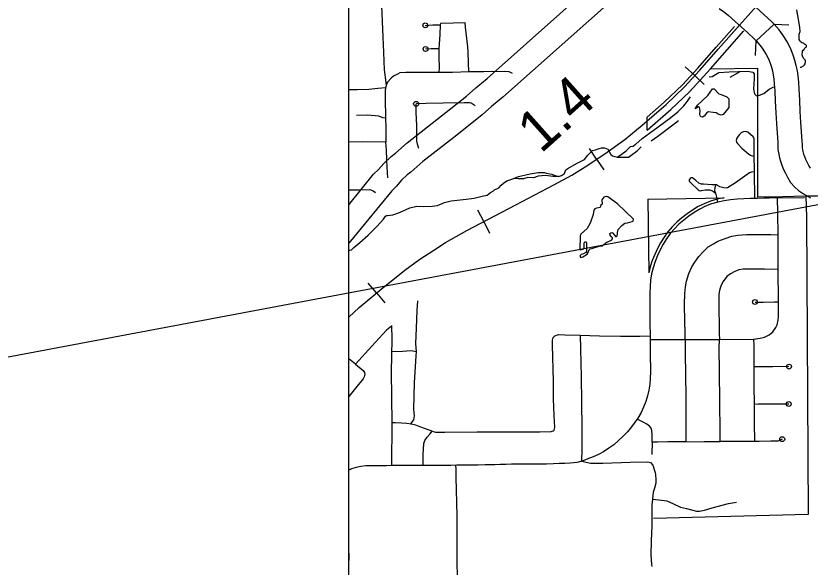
# Model space of a CAD drawing. Extents: x 1367863 to 1368197, y 380048 to 380261.
# Drawn here: x 1367946.24 to 1367977.76, y 380109.6 to 380131.45 of the extents above; entities that cross this region are included whole.
import ezdxf

# ---------------------------------------------------------------- set-up
doc = ezdxf.new("R2010")
doc.units = 0
for name, color, linetype in [('Level 10', 7, 'Continuous'), ('Level 33', 7, 'Continuous'), ('Level 34', 7, 'Continuous'), ('Level 35', 7, 'Continuous'), ('Level 37', 7, 'Continuous'), ('Level 40', 7, 'Continuous'), ('Level 43', 7, 'Continuous'), ('Level 48', 7, 'Continuous'), ('Level 6', 7, 'Continuous'), ('R_Draft', 7, 'Continuous'), ('R_No Plot', 7, 'Continuous')]:
    doc.layers.add(name, color=color, linetype=linetype)

msp = doc.modelspace()

# ---------------------------------------------------------------- linework, layer by layer
at = {"layer": 'Level 10'}
for points in [[(1367959.444, 380123.965), (1367960.435, 380125.172), (1367960.622, 380125.358), (1367960.839, 380125.604), (1367961.127, 380125.881), (1367961.296, 380126.009), (1367961.763, 380126.42), (1367963.132, 380127.482), (1367964.116, 380128.267), (1367964.487, 380128.603), (1367964.936, 380128.963), (1367969.509, 380133.035)], [(1367970.154, 380132.31), (1367965.562, 380128.221), (1367965.116, 380127.864), (1367964.745, 380127.528), (1367963.732, 380126.72), (1367962.381, 380125.672), (1367961.91, 380125.257), (1367961.759, 380125.142), (1367961.54, 380124.932), (1367961.328, 380124.692), (1367961.153, 380124.518), (1367959.444, 380122.436)], [(1367976.324, 380131.118), (1367976.233, 380131.216), (1367975.922, 380131.507), (1367975.438, 380131.938), (1367975.133, 380132.224), (1367974.894, 380132.402), (1367974.719, 380132.53)], [(1367974.147, 380131.746), (1367974.318, 380131.621), (1367974.51, 380131.478), (1367974.783, 380131.222), (1367975.267, 380130.791), (1367975.546, 380130.53), (1367975.614, 380130.457)], [(1367977.772, 380125.411), (1367977.71, 380125.521), (1367977.641, 380125.654), (1367977.588, 380125.761), (1367977.545, 380125.862), (1367977.51, 380125.972), (1367977.48, 380126.075), (1367977.461, 380126.154), (1367977.454, 380126.204), (1367977.45, 380126.238), (1367977.449, 380126.354), (1367977.441, 380126.488), (1367977.386, 380127.24), (1367977.365, 380127.653), (1367977.342, 380128.124), (1367977.32, 380128.534), (1367977.302, 380128.824), (1367977.278, 380129.075), (1367977.249, 380129.27), (1367977.207, 380129.484), (1367977.154, 380129.686), (1367977.098, 380129.858), (1367977.004, 380130.104), (1367976.857, 380130.404), (1367976.654, 380130.714), (1367976.528, 380130.899), (1367976.324, 380131.118), (1367975.614, 380130.457)], [(1367975.614, 380130.457), (1367975.767, 380130.292), (1367975.847, 380130.175), (1367976.013, 380129.922), (1367976.114, 380129.717), (1367976.183, 380129.536), (1367976.222, 380129.414), (1367976.261, 380129.266), (1367976.293, 380129.104), (1367976.315, 380128.958), (1367976.335, 380128.749), (1367976.351, 380128.479), (1367976.373, 380128.074), (1367976.396, 380127.604), (1367976.418, 380127.18), (1367976.473, 380126.424), (1367976.479, 380126.321), (1367976.481, 380126.184), (1367976.491, 380126.082), (1367976.508, 380125.967), (1367976.542, 380125.827), (1367976.582, 380125.691), (1367976.633, 380125.528), (1367976.705, 380125.357), (1367976.777, 380125.212), (1367976.857, 380125.059), (1367976.976, 380124.846), (1367977.144, 380124.657), (1367977.296, 380124.529), (1367977.49, 380124.399), (1367977.773, 380124.236)]]:
    msp.add_lwpolyline(points, dxfattribs=at)
at = {"layer": 'Level 33'}
for points in [[(1367960.702, 380134.32), (1367960.703, 380133.913), (1367960.732, 380132.946), (1367960.749, 380131.842), (1367960.82, 380129.997), (1367960.855, 380129.315), (1367960.912, 380128.815), (1367960.929, 380128.674)], [(1367962.485, 380131.074), (1367962.786, 380131.093), (1367963.081, 380131.098)], [(1367963.081, 380131.098), (1367963.062, 380130.699), (1367963.026, 380130.151), (1367963.022, 380129.798), (1367963.031, 380129.418), (1367963.026, 380129.201)], [(1367963.085, 380131.152), (1367963.081, 380131.098)], [(1367964.072, 380131.175), (1367963.596, 380131.166), (1367963.085, 380131.152)], [(1367964.207, 380129.228), (1367964.198, 380129.585), (1367964.185, 380130.025), (1367964.167, 380130.228), (1367964.108, 380130.772), (1367964.076, 380131.003), (1367964.072, 380131.175)], [(1367962.497, 380130.139), (1367962.723, 380130.16), (1367963.026, 380130.151)], [(1367965.947, 380129.172), (1367965.819, 380129.237), (1367965.629, 380129.246), (1367964.814, 380129.237), (1367964.207, 380129.228), (1367963.56, 380129.205), (1367963.026, 380129.201), (1367962.374, 380129.201), (1367961.709, 380129.201), (1367961.474, 380129.187), (1367961.379, 380129.142), (1367961.225, 380129.056), (1367961.125, 380128.974), (1367960.999, 380128.838), (1367960.949, 380128.748), (1367960.929, 380128.674)], [(1367960.905, 380128.593), (1367960.607, 380128.57), (1367960.246, 380128.534), (1367959.776, 380128.52), (1367959.444, 380128.514)], [(1367960.929, 380128.674), (1367960.905, 380128.593), (1367960.894, 380128.476), (1367960.891, 380128.175), (1367960.908, 380127.394)], [(1367964.461, 380127.879), (1367964.302, 380127.984), (1367964.24, 380128.007), (1367964.023, 380128.007), (1367963.194, 380127.987), (1367962.524, 380127.982), (1367962.119, 380127.964)], [(1367962.232, 380126.193), (1367962.169, 380126.36), (1367962.152, 380126.483), (1367962.144, 380127.11), (1367962.127, 380127.619), (1367962.119, 380127.964)], [(1367960.908, 380127.394), (1367960.796, 380127.412), (1367960.641, 380127.476), (1367960.499, 380127.49), (1367960.177, 380127.508), (1367959.752, 380127.501)], [(1367960.908, 380127.394), (1367960.917, 380127.048), (1367960.924, 380126.439)], [(1367975.563, 380124.212), (1367975.553, 380125.264), (1367975.538, 380125.974), (1367975.538, 380126.599), (1367975.494, 380126.653), (1367975.285, 380126.837), (1367975.241, 380126.857), (1367975.186, 380126.867), (1367975.102, 380126.852), (1367975.023, 380126.817), (1367974.938, 380126.733), (1367974.874, 380126.638), (1367974.834, 380126.574), (1367974.824, 380126.51), (1367974.839, 380126.44), (1367974.869, 380126.385), (1367975.042, 380126.212), (1367975.32, 380125.969), (1367975.385, 380125.924), (1367975.414, 380125.909), (1367975.474, 380125.899), (1367975.533, 380125.894)], [(1367960.924, 380126.439), (1367959.979, 380126.453), (1367959.444, 380126.447)], [(1367961.002, 380125.033), (1367960.972, 380125.452), (1367960.961, 380125.741), (1367960.941, 380126.126), (1367960.924, 380126.439)], [(1367975.553, 380125.264), (1367975.429, 380125.259), (1367975.345, 380125.225), (1367974.79, 380124.828), (1367974.477, 380124.634), (1367974.428, 380124.624), (1367974.338, 380124.629), (1367974.17, 380124.679), (1367974.085, 380124.729), (1367974.041, 380124.748), (1367973.996, 380124.753), (1367973.862, 380124.758), (1367973.525, 380124.773), (1367973.451, 380124.773), (1367973.401, 380124.793), (1367973.337, 380124.818), (1367973.218, 380124.922), (1367973.084, 380125.031), (1367973.039, 380125.036), (1367972.995, 380125.001), (1367972.955, 380124.947), (1367972.955, 380124.927), (1367972.96, 380124.897), (1367973.029, 380124.823), (1367973.317, 380124.555), (1367973.352, 380124.53), (1367973.406, 380124.52), (1367973.451, 380124.525), (1367973.595, 380124.56), (1367973.654, 380124.56), (1367973.758, 380124.55), (1367973.882, 380124.52), (1367973.922, 380124.486), (1367973.996, 380124.416), (1367974.011, 380124.367), (1367974.036, 380124.262), (1367974.084, 380124.067)], [(1367973.996, 380124.753), (1367973.976, 380124.634), (1367973.961, 380124.53), (1367973.996, 380124.416)], [(1367959.444, 380124.557), (1367959.832, 380124.557), (1367960.285, 380124.563), (1367960.356, 380124.546), (1367960.414, 380124.514), (1367960.508, 380124.449)], [(1367977.535, 380124.24), (1367976.137, 380124.228), (1367975.93, 380124.222), (1367975.661, 380124.215), (1367975.393, 380124.206), (1367975.128, 380124.195), (1367974.864, 380124.179), (1367974.603, 380124.156), (1367974.344, 380124.12), (1367974.09, 380124.068), (1367973.842, 380123.995), (1367973.603, 380123.9), (1367973.373, 380123.786), (1367973.153, 380123.656), (1367972.941, 380123.513), (1367972.738, 380123.358), (1367972.547, 380123.191), (1367972.369, 380123.011), (1367972.204, 380122.819), (1367972.053, 380122.616), (1367971.919, 380122.401), (1367971.801, 380122.177), (1367971.696, 380121.945), (1367971.603, 380121.708), (1367971.526, 380121.466), (1367971.467, 380121.22), (1367971.428, 380120.969), (1367971.406, 380120.716), (1367971.395, 380120.461), (1367971.394, 380120.203), (1367971.396, 380119.944), (1367971.397, 380119.682), (1367971.398, 380119.419), (1367971.401, 380119.154), (1367971.404, 380118.888), (1367971.408, 380118.622), (1367971.411, 380118.359), (1367971.413, 380118.099), (1367971.415, 380117.842), (1367971.419, 380117.588), (1367971.422, 380117.339), (1367971.414, 380117.094), (1367971.392, 380116.853), (1367971.353, 380116.617), (1367971.299, 380116.387), (1367971.23, 380116.164), (1367971.145, 380115.943), (1367971.046, 380115.725), (1367970.918, 380115.501), (1367970.777, 380115.302), (1367970.663, 380115.153), (1367970.503, 380114.964), (1367970.332, 380114.785), (1367970.153, 380114.618), (1367969.971, 380114.449), (1367969.771, 380114.313), (1367969.557, 380114.172), (1367969.362, 380114.063), (1367969.146, 380113.974), (1367968.934, 380113.891), (1367968.749, 380113.815), (1367968.494, 380113.751), (1367968.234, 380113.722), (1367968.027, 380113.709), (1367967.793, 380113.699), (1367967.566, 380113.69), (1367967.3, 380113.68)], [(1367976.502, 380120.12), (1367976.49, 380121.4), (1367976.483, 380122.769), (1367976.477, 380123.621), (1367976.463, 380124.263)], [(1367972.802, 380118.622), (1367972.792, 380118.879), (1367972.786, 380119.353), (1367972.773, 380120.006), (1367972.779, 380120.441), (1367972.805, 380120.71), (1367972.85, 380120.934), (1367972.939, 380121.234), (1367973.067, 380121.497), (1367973.176, 380121.689), (1367973.336, 380121.906), (1367973.509, 380122.098), (1367973.713, 380122.29), (1367973.925, 380122.418), (1367974.091, 380122.521), (1367974.385, 380122.629), (1367974.654, 380122.713), (1367974.89, 380122.757), (1367975.236, 380122.777), (1367975.824, 380122.777), (1367976.195, 380122.783), (1367976.483, 380122.769)], [(1367976.49, 380121.4), (1367975.946, 380121.414), (1367975.102, 380121.407), (1367974.922, 380121.382), (1367974.762, 380121.318), (1367974.59, 380121.222), (1367974.449, 380121.113), (1367974.302, 380120.914), (1367974.232, 380120.78), (1367974.18, 380120.652), (1367974.155, 380120.562), (1367974.136, 380120.422), (1367974.136, 380120.178), (1367974.136, 380119.705), (1367974.142, 380119.302), (1367974.148, 380118.854), (1367974.157, 380118.622)], [(1367961.891, 380115.265), (1367962.029, 380115.442), (1367962.051, 380115.593), (1367962.036, 380115.864), (1367962.059, 380116.898), (1367962.127, 380117.978), (1367962.142, 380118.136), (1367962.104, 380118.461), (1367962.134, 380119.065), (1367962.165, 380119.767), (1367962.187, 380120.159)], [(1367975.506, 380118.635), (1367975.773, 380118.668), (1367975.94, 380118.719), (1367976.125, 380118.809), (1367976.272, 380118.931), (1367976.4, 380119.091), (1367976.451, 380119.206), (1367976.49, 380119.385), (1367976.502, 380119.545), (1367976.496, 380119.788), (1367976.502, 380120.12)], [(1367975.569, 380120.107), (1367975.895, 380120.107), (1367976.343, 380120.114), (1367976.502, 380120.12)], [(1367961.14, 380119.148), (1367960.942, 380118.989), (1367960.369, 380118.363), (1367959.72, 380117.646)], [(1367961.14, 380119.173), (1367961.153, 380118.638), (1367961.135, 380117.34), (1367961.154, 380115.317)], [(1367962.759, 380114.984), (1367962.887, 380114.95), (1367963.258, 380114.95), (1367964.543, 380114.963), (1367965.612, 380114.957), (1367967.032, 380114.957), (1367967.486, 380114.97), (1367967.556, 380114.995), (1367967.601, 380115.021), (1367967.627, 380115.13), (1367967.601, 380115.61), (1367967.569, 380116.275), (1367967.569, 380116.953), (1367967.531, 380118.409), (1367967.537, 380118.601), (1367967.556, 380118.697), (1367967.627, 380118.768), (1367967.767, 380118.819), (1367968.023, 380118.812), (1367968.637, 380118.787)], [(1367968.637, 380118.787), (1367969.392, 380118.768), (1367970.23, 380118.755), (1367970.998, 380118.755), (1367971.406, 380118.762)], [(1367968.637, 380118.787), (1367968.65, 380118.249), (1367968.669, 380117.136), (1367968.682, 380116.141), (1367968.695, 380115.117), (1367968.701, 380114.464), (1367968.695, 380114.099), (1367968.689, 380113.959), (1367968.682, 380113.798)], [(1367971.408, 380118.616), (1367972.802, 380118.622)], [(1367972.802, 380118.622), (1367972.802, 380118.078), (1367972.821, 380116.344), (1367972.827, 380115.064), (1367972.827, 380114.565)], [(1367972.802, 380118.622), (1367974.157, 380118.622)], [(1367974.189, 380114.578), (1367974.182, 380114.956), (1367974.176, 380116.152), (1367974.157, 380117.349), (1367974.15, 380118.296), (1367974.157, 380118.622)], [(1367974.157, 380118.622), (1367975.506, 380118.635)], [(1367975.506, 380118.635), (1367975.526, 380118.398), (1367975.526, 380117.534), (1367975.526, 380116.799), (1367975.532, 380116.05), (1367975.538, 380115.301), (1367975.551, 380114.584)], [(1367962.142, 380118.136), (1367961.923, 380118.167), (1367961.584, 380118.151), (1367961.146, 380118.137)], [(1367959.72, 380117.646), (1367959.444, 380117.851)], [(1367959.72, 380117.646), (1367960.022, 380117.397), (1367960.067, 380117.314), (1367960.082, 380117.246), (1367960.052, 380117.14), (1367960.014, 380117.065), (1367959.773, 380116.763), (1367959.444, 380116.361)], [(1367976.918, 380117.547), (1367976.272, 380117.541), (1367975.78, 380117.541), (1367975.526, 380117.534)], [(1367976.905, 380116.063), (1367976.579, 380116.063), (1367975.978, 380116.063), (1367975.69, 380116.056), (1367975.532, 380116.05)], [(1367961.154, 380115.317), (1367961.142, 380113.625)], [(1367962.759, 380114.984), (1367962.592, 380115.042), (1367962.311, 380115.15), (1367962.106, 380115.227), (1367961.921, 380115.259), (1367961.754, 380115.291), (1367961.537, 380115.304), (1367961.3, 380115.317), (1367961.154, 380115.317)], [(1367971.484, 380114.552), (1367971.484, 380114.84), (1367971.478, 380115.02), (1367971.452, 380115.103), (1367971.388, 380115.18), (1367971.279, 380115.263), (1367971.132, 380115.34), (1367970.895, 380115.468)], [(1367962.394, 380113.627), (1367962.4, 380114.062), (1367962.432, 380114.504), (1367962.471, 380114.613), (1367962.56, 380114.747), (1367962.669, 380114.862), (1367962.759, 380114.984)], [(1367976.65, 380114.668), (1367976.49, 380114.591), (1367976.202, 380114.591), (1367975.728, 380114.584), (1367975.551, 380114.584)], [(1367971.484, 380114.552), (1367971.479, 380114.061)], [(1367972.827, 380114.565), (1367972.105, 380114.559), (1367971.695, 380114.552), (1367971.484, 380114.552)], [(1367972.827, 380114.565), (1367973.549, 380114.572), (1367974.189, 380114.578)], [(1367975.551, 380114.584), (1367974.189, 380114.578)], [(1367967.3, 380113.68), (1367967.061, 380113.677), (1367966.811, 380113.68), (1367966.626, 380113.677), (1367966.376, 380113.674), (1367966.143, 380113.674), (1367965.899, 380113.676), (1367965.695, 380113.663), (1367965.461, 380113.661), (1367965.244, 380113.658), (1367965.049, 380113.655), (1367964.857, 380113.648), (1367964.569, 380113.642), (1367964.396, 380113.645), (1367964.169, 380113.642), (1367963.952, 380113.639), (1367963.731, 380113.635), (1367963.504, 380113.632), (1367963.296, 380113.632)], [(1367963.296, 380113.632), (1367961.262, 380113.62), (1367961.163, 380113.62), (1367960.945, 380113.618), (1367960.732, 380113.616), (1367960.522, 380113.616), (1367960.318, 380113.614), (1367960.12, 380113.607), (1367959.926, 380113.587), (1367959.737, 380113.55), (1367959.554, 380113.491), (1367959.444, 380113.437)], [(1367963.826, 380107.793), (1367963.796, 380108.304), (1367963.762, 380108.973), (1367963.748, 380110.034), (1367963.743, 380111.627), (1367963.714, 380113.161), (1367963.705, 380113.479), (1367963.695, 380113.635)], [(1367959.444, 380110.156), (1367959.448, 380110.111), (1367959.444, 380109.864)]]:
    msp.add_lwpolyline(points, dxfattribs=at)
for centre in [(1367962.485, 380131.074), (1367962.497, 380130.139), (1367962.119, 380127.964), (1367975.569, 380120.107), (1367976.918, 380117.547), (1367976.905, 380116.063), (1367976.65, 380114.668)]:
    msp.add_circle(centre, 0.097, dxfattribs=at)
at = {"layer": 'Level 34'}
for points in [[(1367968.682, 380113.798), (1367969.043, 380113.722), (1367969.525, 380113.722), (1367970.611, 380113.752), (1367971.316, 380113.77), (1367971.425, 380113.746), (1367971.509, 380113.638), (1367971.6, 380113.39), (1367971.618, 380113.27), (1367971.636, 380113.058), (1367971.63, 380112.92), (1367971.582, 380112.733), (1367971.534, 380112.57), (1367971.509, 380112.431), (1367971.503, 380112.298)], [(1367971.503, 380112.298), (1367971.481, 380112.063), (1367971.481, 380111.63), (1367971.468, 380111.222), (1367971.451, 380110.654), (1367971.439, 380110.091), (1367971.46, 380109.7), (1367971.477, 380109.616)], [(1367971.503, 380112.298), (1367971.757, 380112.268), (1367972.064, 380112.22), (1367972.33, 380112.111), (1367972.613, 380111.979), (1367972.854, 380111.924), (1367973.047, 380111.864), (1367973.252, 380111.822), (1367973.367, 380111.822), (1367973.566, 380111.858), (1367973.873, 380111.954), (1367974.516, 380112.117), (1367974.83, 380112.178)]]:
    msp.add_lwpolyline(points, dxfattribs=at)
at = {"layer": 'Level 35'}
for points in [[(1367977.363, 380129.414), (1367977.396, 380129.42), (1367977.497, 380129.467), (1367977.53, 380129.504), (1367977.556, 380129.546), (1367977.56, 380129.584), (1367977.568, 380129.613), (1367977.577, 380129.63), (1367977.577, 380129.663), (1367977.572, 380129.693), (1367977.547, 380129.71), (1367977.53, 380129.726), (1367977.514, 380129.739), (1367977.505, 380129.764), (1367977.48, 380129.789), (1367977.468, 380129.831), (1367977.442, 380129.902), (1367977.442, 380129.944), (1367977.451, 380129.994), (1367977.451, 380130.045), (1367977.484, 380130.087), (1367977.518, 380130.116), (1367977.539, 380130.154), (1367977.572, 380130.191), (1367977.602, 380130.216), (1367977.606, 380130.246), (1367977.606, 380130.279), (1367977.585, 380130.304), (1367977.535, 380130.33), (1367977.518, 380130.342), (1367977.48, 380130.363), (1367977.447, 380130.376), (1367977.409, 380130.392), (1367977.371, 380130.422), (1367977.35, 380130.476), (1367977.325, 380130.518), (1367977.325, 380130.577), (1367977.325, 380130.627), (1367977.321, 380130.665), (1367977.321, 380130.702), (1367977.321, 380130.723), (1367977.359, 380130.828), (1367977.346, 380130.991), (1367977.308, 380131.239), (1367977.225, 380131.683)], [(1367973.2, 380127.771), (1367973.284, 380127.909), (1367973.703, 380128.295), (1367973.883, 380128.555), (1367973.942, 380128.555), (1367974.13, 380128.354), (1367974.227, 380128.333), (1367974.448, 380128.236), (1367974.528, 380128.157), (1367974.536, 380128.052), (1367974.532, 380127.926), (1367974.524, 380127.817), (1367974.428, 380127.683), (1367974.302, 380127.541), (1367974.231, 380127.52), (1367974.105, 380127.558), (1367974.03, 380127.608), (1367973.904, 380127.625), (1367973.716, 380127.641), (1367973.644, 380127.599), (1367973.548, 380127.47), (1367973.485, 380127.44), (1367973.435, 380127.449), (1367973.389, 380127.482), (1367973.385, 380127.541), (1367973.385, 380127.57), (1367973.393, 380127.687), (1367973.381, 380127.767), (1367973.36, 380127.813), (1367973.322, 380127.838), (1367973.2, 380127.771)], [(1367975.554, 380128.356), (1367975.625, 380128.281), (1367975.742, 380128.302), (1367975.918, 380128.377), (1367976.128, 380128.541), (1367976.32, 380128.633)], [(1367967.769, 380125.08), (1367967.886, 380125.118), (1367968.011, 380125.206), (1367968.058, 380125.344), (1367968.145, 380125.399), (1367968.485, 380125.595), (1367968.807, 380125.763), (1367968.929, 380125.926), (1367969.117, 380126.111), (1367969.243, 380126.136), (1367969.381, 380126.19), (1367969.481, 380126.224), (1367969.594, 380126.224), (1367969.728, 380126.169), (1367969.846, 380125.96), (1367969.909, 380125.901), (1367970.101, 380125.843)], [(1367959.444, 380122.153), (1367959.489, 380122.156), (1367959.556, 380122.181), (1367959.644, 380122.265), (1367959.891, 380122.47), (1367960.218, 380122.759), (1367960.565, 380123.103), (1367960.825, 380123.392), (1367960.9, 380123.505), (1367960.951, 380123.53), (1367960.98, 380123.538), (1367961.194, 380123.568), (1367961.462, 380123.656), (1367961.872, 380123.836), (1367962.148, 380123.903), (1367962.404, 380123.895), (1367962.76, 380123.907), (1367962.973, 380123.936), (1367963.25, 380124.05), (1367963.505, 380124.121), (1367964.113, 380124.184), (1367964.418, 380124.221), (1367964.737, 380124.301), (1367964.942, 380124.343), (1367965.076, 380124.443), (1367965.197, 380124.515), (1367965.239, 380124.561), (1367965.323, 380124.594), (1367965.398, 380124.636), (1367965.49, 380124.741), (1367965.591, 380124.816), (1367965.721, 380124.908), (1367965.993, 380125.001), (1367966.177, 380125.089), (1367966.642, 380125.189), (1367966.96, 380125.239), (1367967.216, 380125.239), (1367967.287, 380125.218), (1367967.425, 380125.189), (1367967.501, 380125.176), (1367967.597, 380125.135), (1367967.769, 380125.08)], [(1367967.769, 380125.08), (1367967.551, 380125.08), (1367967.258, 380125.118), (1367966.964, 380125.101), (1367966.772, 380125.034), (1367966.558, 380125.047), (1367966.378, 380124.984), (1367966.29, 380124.996), (1367966.173, 380124.984), (1367965.993, 380125.001)], [(1367969.643, 380124.295), (1367969.643, 380124.295), (1367969.564, 380124.259), (1367969.485, 380124.152), (1367969.5, 380123.986), (1367969.437, 380123.935), (1367969.437, 380123.879), (1367969.409, 380123.848), (1367969.354, 380123.836), (1367969.279, 380123.832), (1367969.212, 380123.804), (1367969.176, 380123.745), (1367969.14, 380123.578), (1367969.03, 380123.226), (1367968.903, 380123.017), (1367968.654, 380122.795), (1367968.634, 380122.732), (1367968.618, 380122.189), (1367968.642, 380122.174), (1367968.733, 380122.201), (1367968.776, 380122.217), (1367968.776, 380122.221), (1367968.788, 380122.265), (1367968.792, 380122.407), (1367968.804, 380122.474), (1367968.824, 380122.498), (1367968.871, 380122.498), (1367968.883, 380122.463), (1367968.883, 380122.352), (1367968.879, 380122.17), (1367968.883, 380122.114), (1367968.852, 380122.067), (1367968.769, 380122.019), (1367968.666, 380121.992), (1367968.63, 380121.948), (1367968.626, 380121.893), (1367968.654, 380121.869), (1367968.733, 380121.897), (1367968.911, 380122), (1367968.951, 380122.075), (1367968.982, 380122.17), (1367969.03, 380122.213), (1367969.136, 380122.245), (1367969.386, 380122.316), (1367969.473, 380122.328), (1367969.52, 380122.336), (1367969.568, 380122.391), (1367969.686, 380122.474), (1367969.876, 380122.565), (1367969.92, 380122.617), (1367969.92, 380122.649), (1367969.88, 380122.692), (1367969.825, 380122.763), (1367969.809, 380122.823), (1367969.845, 380122.85), (1367969.884, 380122.862), (1367969.916, 380122.846), (1367970.003, 380122.743), (1367970.034, 380122.704), (1367970.074, 380122.7), (1367970.102, 380122.728), (1367970.117, 380122.795), (1367970.117, 380122.866), (1367970.141, 380122.977), (1367970.288, 380123.135), (1367970.402, 380123.23), (1367970.513, 380123.246), (1367970.699, 380123.294), (1367970.735, 380123.313), (1367970.746, 380123.385)], [(1367970.746, 380123.385), (1367970.106, 380123.994), (1367969.722, 380124.275), (1367969.666, 380124.291)]]:
    msp.add_lwpolyline(points, dxfattribs=at)
at = {"layer": 'Level 37'}
for points in [[(1367976.323, 380131.119), (1367976.905, 380131.099)], [(1367975.594, 380129.875), (1367975.614, 380130.457)]]:
    msp.add_lwpolyline(points, dxfattribs=at)
at = {"layer": 'Level 40'}
for p, q in [((1367973.177, 380129.08), (1367972.802, 380129.429)), ((1367973.177, 380129.08), (1367973.551, 380128.73)), ((1367969.283, 380125.769), (1367969, 380126.196)), ((1367969.283, 380125.769), (1367969.566, 380125.342)), ((1367964.802, 380123.293), (1367964.566, 380123.748)), ((1367964.802, 380123.293), (1367965.038, 380122.839)), ((1367960.545, 380120.467), (1367960.216, 380120.859)), ((1367960.545, 380120.467), (1367960.874, 380120.074))]:
    msp.add_line(p, q, dxfattribs=at)
for points in [[(1367959.444, 380119.5), (1367959.854, 380119.887), (1367960.728, 380120.619), (1367961.678, 380121.374), (1367962.268, 380121.8), (1367962.826, 380122.161), (1367963.285, 380122.467), (1367964.137, 380122.947), (1367966.071, 380123.953), (1367967.579, 380124.751), (1367968.3, 380125.133), (1367968.835, 380125.472), (1367969.611, 380125.986), (1367970.398, 380126.554), (1367971.086, 380127.112), (1367972.037, 380127.942), (1367972.769, 380128.642), (1367973.381, 380129.298), (1367974.113, 380130.128), (1367975.172, 380131.331), (1367976.298, 380132.599)], [(1367959.444, 380119.5), (1367959.854, 380119.887), (1367960.728, 380120.619), (1367961.678, 380121.374), (1367962.268, 380121.8), (1367962.826, 380122.161), (1367963.285, 380122.467), (1367964.137, 380122.947), (1367966.071, 380123.953), (1367967.579, 380124.751), (1367968.3, 380125.133), (1367968.835, 380125.472), (1367969.611, 380125.986), (1367970.398, 380126.554), (1367971.086, 380127.112), (1367972.037, 380127.942), (1367972.769, 380128.642), (1367973.381, 380129.298), (1367974.113, 380130.128), (1367974.935, 380131.062)]]:
    msp.add_lwpolyline(points, dxfattribs=at)
at = {"layer": 'Level 43'}
for points in [[(1367973.753, 380129.027), (1367973.874, 380129.048), (1367974.13, 380129.207), (1367974.54, 380129.236), (1367975.29, 380129.261), (1367975.478, 380129.215), (1367975.533, 380129.148), (1367975.541, 380128.972), (1367975.512, 380128.545), (1367975.554, 380128.356)], [(1367974.587, 380129.017), (1367974.985, 380129.251), (1367975.29, 380129.261), (1367975.478, 380129.215), (1367975.533, 380129.148), (1367975.541, 380128.972), (1367975.512, 380128.545), (1367975.554, 380128.356)], [(1367970.101, 380125.843), (1367970.206, 380125.91), (1367970.457, 380126.098), (1367970.629, 380126.266), (1367970.729, 380126.283), (1367970.821, 380126.362), (1367970.834, 380126.37), (1367971.085, 380126.593), (1367971.525, 380126.903), (1367972.224, 380127.426), (1367972.505, 380127.644), (1367972.74, 380127.883), (1367972.853, 380128.013), (1367973.012, 380128.243)], [(1367971.445, 380126.493), (1367971.714, 380126.682), (1367972.413, 380127.206), (1367972.534, 380127.3)], [(1367970.101, 380125.843), (1367970.542, 380125.843), (1367970.646, 380125.91), (1367970.898, 380126.098), (1367971.057, 380126.254)]]:
    msp.add_lwpolyline(points, dxfattribs=at)
at = {"layer": 'Level 6'}
for points in [[(1367971.294, 380126.92), (1367971.289, 380127.441), (1367971.959, 380128.027), (1367972.687, 380128.722), (1367973.296, 380129.375), (1367974.027, 380130.204), (1367974.757, 380131.032)], [(1367973.809, 380129.345), (1367975.131, 380130.852)], [(1367971.294, 380126.92), (1367972.226, 380127.735), (1367972.969, 380128.444), (1367973.809, 380129.345)], [(1367973.809, 380129.345), (1367975.67, 380129.378)], [(1367973.809, 380129.345), (1367975.67, 380129.378)], [(1367975.67, 380129.378), (1367975.67, 380124.262)], [(1367975.67, 380129.378), (1367975.67, 380124.262)], [(1367983.164, 380124.401), (1367982.713, 380124.393), (1367981.893, 380124.377), (1367980.878, 380124.359), (1367979.776, 380124.338), (1367979.121, 380124.326), (1367978.702, 380124.318), (1367978.037, 380124.306), (1367977.589, 380124.298)], [(1367971.318, 380124.181), (1367974.343, 380124.237)], [(1367971.318, 380124.181), (1367971.359, 380121.265)], [(1367974.343, 380124.237), (1367974.062, 380124.18), (1367973.804, 380124.104), (1367973.556, 380124.005), (1367973.318, 380123.887), (1367973.091, 380123.753), (1367972.874, 380123.606), (1367972.665, 380123.447), (1367972.468, 380123.275), (1367972.284, 380123.089), (1367972.113, 380122.891), (1367971.958, 380122.68), (1367971.819, 380122.459), (1367971.697, 380122.227), (1367971.59, 380121.99), (1367971.494, 380121.747), (1367971.415, 380121.497), (1367971.359, 380121.265)], [(1367977.589, 380124.298), (1367976.658, 380124.28), (1367975.67, 380124.262)], [(1367977.589, 380124.298), (1367976.658, 380124.28), (1367975.67, 380124.262)], [(1367977.589, 380124.298), (1367977.608, 380123.467), (1367977.679, 380111.685)], [(1367977.679, 380111.685), (1367971.546, 380111.526)]]:
    msp.add_lwpolyline(points, dxfattribs=at)
at = {"layer": 'R_Draft'}
msp.add_lwpolyline([(1368027.28, 380133.22), (1367942.971, 380117.362)], dxfattribs=at)
at = {"layer": 'R_No Plot'}
msp.add_lwpolyline([(1367959.444, 380177.46), (1368103.344, 380177.46), (1368103.344, 380096.865), (1367959.444, 380096.865)], close=True, dxfattribs=at)

# ---------------------------------------------------------------- texts
at = {"layer": 'Level 48'}
msp.add_text('1.4', height=1.6394, rotation=41.773, dxfattribs=at).set_placement((1367967.067, 380125.963))

doc.saveas('drawing.dxf')
